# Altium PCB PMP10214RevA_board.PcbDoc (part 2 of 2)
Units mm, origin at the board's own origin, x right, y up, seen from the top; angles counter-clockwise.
Board outline 108.2 x 92.71 mm, 6 copper layers (Top Layer, MidLayer1, MidLayer2, MidLayer3, MidLayer4, Bottom Layer), stack 1.557 mm thick; 122 components, 44 nets, 289 pads, 1298 vias.
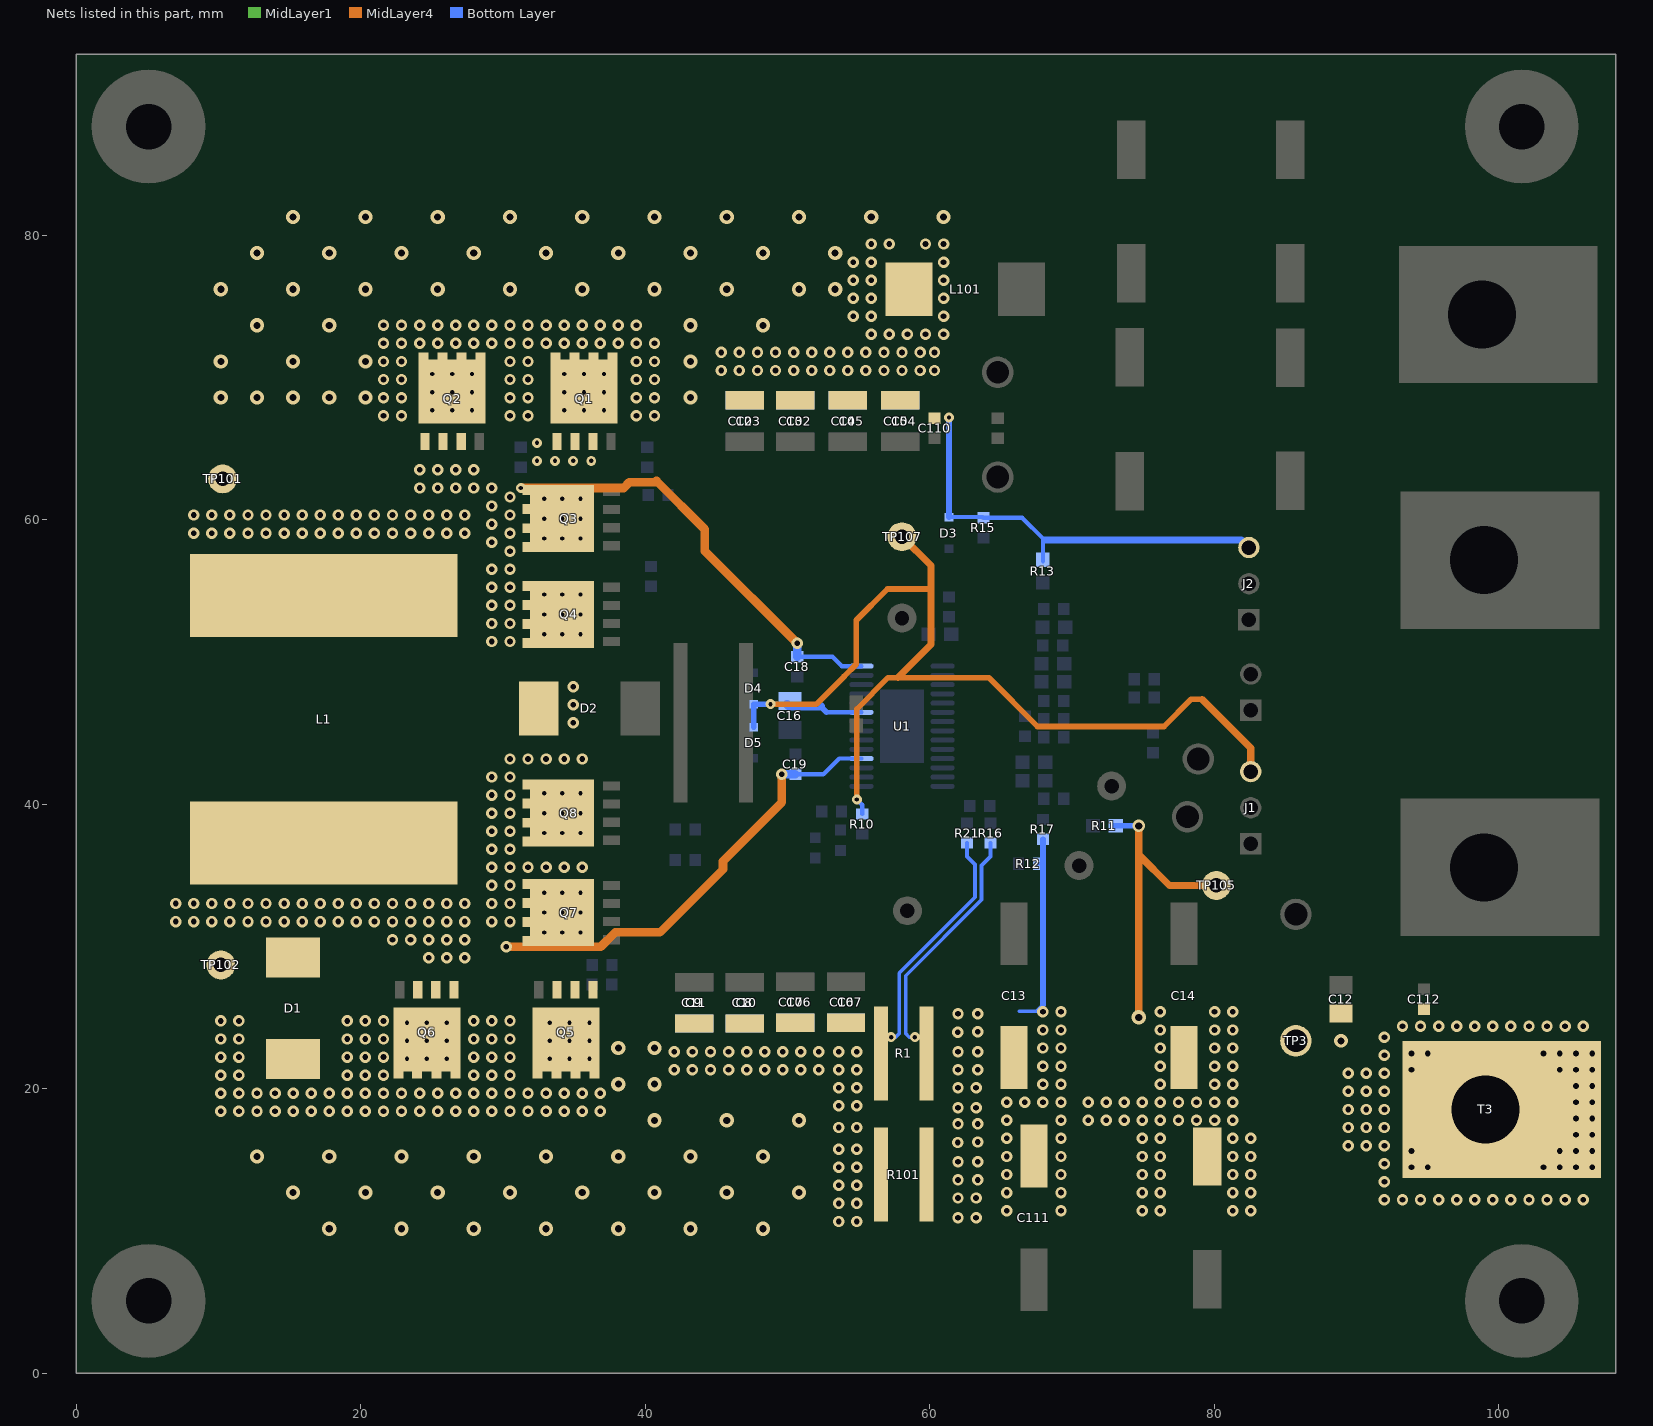
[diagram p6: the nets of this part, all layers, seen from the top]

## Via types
v1: diameter 0.8, hole 0.4, Top Layer to Bottom Layer, tented both sides, 696 vias
v2: diameter 0.8, hole 0.4, Top Layer to Bottom Layer, 220 vias
v3: diameter 0.7, hole 0.3, Top Layer to Bottom Layer, 142 vias
v4: diameter 0.813, hole 0.4, Top Layer to Bottom Layer, 112 vias
v5: diameter 1, hole 0.5, Top Layer to Bottom Layer, tented both sides, 74 vias
v6: diameter 0.7, hole 0.3, Top Layer to Bottom Layer, tented both sides, 25 vias
v7: diameter 0.6, hole 0.3, Top Layer to Bottom Layer, 15 vias
v8: diameter 0.7, hole 0.3, Top Layer to Bottom Layer, tented bottom, 5 vias
v9: diameter 0.6, hole 0.3, Top Layer to Bottom Layer, tented bottom, 3 vias
v10: diameter 0.965, hole 0.5, Top Layer to Bottom Layer, 2 vias
v11: diameter 0.65, hole 0.3, Top Layer to Bottom Layer, tented bottom, 2 vias
v12: diameter 0.67, hole 0.3, Top Layer to Bottom Layer, tented bottom, 1 vias
v13: diameter 0.9, hole 0.5, Top Layer to Bottom Layer, 1 vias

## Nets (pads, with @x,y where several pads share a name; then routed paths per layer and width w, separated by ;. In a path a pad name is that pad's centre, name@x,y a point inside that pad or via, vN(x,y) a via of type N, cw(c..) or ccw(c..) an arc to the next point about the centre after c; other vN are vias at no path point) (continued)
SW1: C18.1 D2.1 L1.1 Q1.1 Q1.2 Q1.3 Q2.1 Q2.2 Q2.3 Q3.5 Q3.6 Q3.7 Q3.8 Q3.9 Q4.5 Q4.6 Q4.7 Q4.8 Q4.9 TP101.1 U1.28 | length 31
  MidLayer4 w0.61: v3(31.242,62.23) 38.471,62.23 38.868,62.627 40.69,62.627 40.784,62.721 44.183,59.322 44.183,57.798 v2(50.673,51.308)
  Bottom Layer w0.305: C18.1@50.673,50.357 53.148,50.357 53.798,49.707 U1.28@55.189,49.707
  Bottom Layer w0.61: C18.1@50.673,50.357 v2(50.673,51.308)
  other v1: 34.925,45.72 34.925,46.99 34.925,48.26 29.21,51.435 30.48,51.435 29.21,52.705 30.48,52.705 29.21,53.975 30.48,53.975 29.21,55.245 30.48,55.245 29.21,56.515 30.48,56.515 30.48,57.785 29.21,58.42 8.255,59.055 9.525,59.055 12.065,59.055 14.605,59.055 17.145,59.055 19.685,59.055 22.225,59.055 24.765,59.055 26.035,59.055 27.305,59.055 30.48,59.055 29.21,59.69 8.255,60.325 9.525,60.325 12.065,60.325 14.605,60.325 17.145,60.325 19.685,60.325 22.225,60.325 24.765,60.325 26.035,60.325 27.305,60.325 30.48,60.325 29.21,60.96 30.48,61.595 24.13,62.23 25.4,62.23 26.67,62.23 27.94,62.23 29.21,62.23 24.13,63.5 25.4,63.5 26.67,63.5 27.94,63.5
  other v2: 10.795,59.055 13.335,59.055 15.875,59.055 18.415,59.055 20.955,59.055 23.495,59.055 10.795,60.325 13.335,60.325 15.875,60.325 18.415,60.325 20.955,60.325 23.495,60.325
  other v3: 32.893,51.943 34.163,51.943 35.433,51.943 32.893,53.34 34.163,53.34 35.433,53.34 32.893,54.737 34.163,54.737 35.433,54.737 32.893,58.674 34.163,58.674 35.433,58.674 32.893,60.071 34.163,60.071 35.433,60.071 32.893,61.468 34.163,61.468 35.433,61.468
  other v6: 32.385,64.135 33.655,64.135 34.925,64.135 36.195,64.135 32.385,65.405
SW2: C19.2 D1.2 L1.2 Q5.1 Q5.2 Q5.3 Q6.1 Q6.2 Q6.3 Q7.5 Q7.6 Q7.7 Q7.8 Q7.9 Q8.5 Q8.6 Q8.7 Q8.8 Q8.9 TP102.1 U1.18 | length 31.9
  MidLayer4 w0.61: v2(30.226,29.972) 36.857,29.972 37.873,30.988 41.021,30.988 45.45,35.417 45.45,35.984 49.592,40.126 v2(49.592,42.099)
  Bottom Layer w0.305: C19.2@50.546,42.099 52.513,42.099 53.621,43.207 U1.18@55.189,43.207
  Bottom Layer w0.61: v2(49.592,42.099) C19.2@50.546,42.099
  other v1: 24.765,29.21 26.035,29.21 27.305,29.21 22.225,30.48 23.495,30.48 24.765,30.48 26.035,30.48 27.305,30.48 6.985,31.75 8.255,31.75 9.525,31.75 12.065,31.75 14.605,31.75 17.145,31.75 19.685,31.75 22.225,31.75 24.765,31.75 26.035,31.75 27.305,31.75 29.21,31.75 30.48,31.75 6.985,33.02 8.255,33.02 9.525,33.02 12.065,33.02 14.605,33.02 17.145,33.02 19.685,33.02 22.225,33.02 24.765,33.02 26.035,33.02 27.305,33.02 29.21,33.02 30.48,33.02 29.21,34.29 30.48,34.29 29.21,35.56 30.48,35.56 31.75,35.56 33.02,35.56 34.29,35.56 35.56,35.56 29.21,36.83 30.48,36.83 29.21,38.1 30.48,38.1 29.21,39.37 30.48,39.37 29.21,40.64 30.48,40.64 29.21,41.91 30.48,41.91 30.48,43.18 31.75,43.18 33.02,43.18 34.29,43.18 35.56,43.18
  other v2: 10.795,31.75 13.335,31.75 15.875,31.75 18.415,31.75 20.955,31.75 23.495,31.75 10.795,33.02 13.335,33.02 15.875,33.02 18.415,33.02 20.955,33.02 23.495,33.02
  other v3: 32.893,30.988 34.163,30.988 35.433,30.988 32.893,32.385 34.163,32.385 35.433,32.385 32.893,33.782 34.163,33.782 35.433,33.782 32.893,37.973 34.163,37.973 35.433,37.973 32.893,39.37 34.163,39.37 35.433,39.37 32.893,40.767 34.163,40.767 35.433,40.767
VCC: C16.2 D4.2 D5.2 J1.3 R10.2 TP107.1 U1.23 | length 79.2
  MidLayer1 w0.254: v8@54.864,40.132 v8(54.864,40.332)
  MidLayer4 w0.4: v8(54.864,40.332) 54.864,46.702 57.057,48.895 57.748,48.895 64.135,48.895 67.564,45.466 76.454,45.466 78.359,47.371 79.121,47.371
  MidLayer4 w0.406: v6(48.789,47.033) 52.032,47.033 53.522,48.523 53.525,48.523 53.966,48.964 53.966,48.967 54.829,49.829 54.829,52.924 57.023,55.118 60.071,55.118
  MidLayer4 w0.5: 57.748,48.895 60.071,51.218 60.071,55.118 60.071,56.769 TP107.1@58.039,58.801 ; 79.121,47.371 82.55,43.942 J1.3@82.55,42.291
  Bottom Layer w0.305: 52.73,46.457 U1.23@55.189,46.457 ; v8(54.864,40.332) 55.245,39.951 R10.2@55.245,39.308
  Bottom Layer w0.406: D5.2@47.625,45.423 D4.2@47.625,47.033 v6(48.789,47.033) C16.2@49.954,47.033 ; 52.309,46.878 52.73,46.457
  Bottom Layer w0.61: C16.2@49.954,47.033 50.109,46.878 52.309,46.878
VIN: C2.1 C3.1 C4.1 C5.1 C102.1 C103.1 C104.1 C105.1 C110.1 D3.2 J2.3 L101.2 Q1.5 Q1.6 Q1.7 Q1.8 Q1.9 Q2.5 Q2.6 Q2.7 Q2.8 Q2.9 R13.2 R15.2 | length 30.5
  Bottom Layer w0.305: D3.2@61.341,60.184 R15.2@63.705,60.184 ; R15.2@63.754,60.136 66.483,60.136 67.945,58.674 ; R13.2@67.945,57.088 67.945,57.15 67.945,58.674 ; 68.056,58.563 67.945,58.674
  Bottom Layer w0.4: D3.2@61.341,60.184 v3(61.341,67.183)
  Bottom Layer w0.5: 68.056,58.563 81.899,58.563 J2.3@82.423,58.039
  other v1: 21.59,67.31 22.86,67.31 30.48,67.31 31.75,67.31 39.37,67.31 40.64,67.31 21.59,68.58 22.86,68.58 30.48,68.58 31.75,68.58 39.37,68.58 40.64,68.58 21.59,69.85 22.86,69.85 30.48,69.85 31.75,69.85 39.37,69.85 40.64,69.85 60.325,70.485 21.59,71.12 22.86,71.12 30.48,71.12 31.75,71.12 39.37,71.12 40.64,71.12 60.325,71.755 21.59,72.39 22.86,72.39 24.13,72.39 25.4,72.39 26.67,72.39 27.94,72.39 29.21,72.39 30.48,72.39 31.75,72.39 33.02,72.39 34.29,72.39 35.56,72.39 36.83,72.39 38.1,72.39 39.37,72.39 40.64,72.39 55.88,73.025 57.15,73.025 58.42,73.025 59.69,73.025 60.96,73.025 21.59,73.66 22.86,73.66 24.13,73.66 25.4,73.66 26.67,73.66 27.94,73.66 29.21,73.66 30.48,73.66 31.75,73.66 33.02,73.66 34.29,73.66 35.56,73.66 36.83,73.66 38.1,73.66 39.37,73.66 54.61,74.295 55.88,74.295 60.96,74.295 54.61,75.565 55.88,75.565 60.96,75.565 54.61,76.835 55.88,76.835 60.96,76.835 54.61,78.105 55.88,78.105 60.96,78.105 55.88,79.375 57.15,79.375 59.69,79.375 60.96,79.375
  other v2: 45.339,70.485 46.609,70.485 47.879,70.485 49.149,70.485 50.419,70.485 51.689,70.485 52.959,70.485 54.229,70.485 55.499,70.485 56.769,70.485 58.039,70.485 59.309,70.485 45.339,71.755 46.609,71.755 47.879,71.755 49.149,71.755 50.419,71.755 51.689,71.755 52.959,71.755 54.229,71.755 55.499,71.755 56.769,71.755 58.039,71.755 59.309,71.755
  other v3: 25.019,67.691 26.416,67.691 27.813,67.691 34.29,67.691 35.687,67.691 37.084,67.691 25.019,68.961 26.416,68.961 27.813,68.961 34.29,68.961 35.687,68.961 37.084,68.961 25.019,70.231 26.416,70.231 27.813,70.231 34.29,70.231 35.687,70.231 37.084,70.231
  other v5: 10.16,68.58 12.7,68.58 15.24,68.58 17.78,68.58 20.32,68.58 43.18,68.58 10.16,71.12 15.24,71.12 20.32,71.12 43.18,71.12 12.7,73.66 17.78,73.66 43.18,73.66 48.26,73.66 10.16,76.2 15.24,76.2 20.32,76.2 25.4,76.2 30.48,76.2 35.56,76.2 40.64,76.2 45.72,76.2 50.8,76.2 53.34,76.2 12.7,78.74 17.78,78.74 22.86,78.74 27.94,78.74 33.02,78.74 38.1,78.74 43.18,78.74 48.26,78.74 53.34,78.74 15.24,81.28 20.32,81.28 25.4,81.28 30.48,81.28 35.56,81.28 40.64,81.28 45.72,81.28 50.8,81.28 55.88,81.28 60.96,81.28
VOSNS+: C6.1 C7.1 C8.1 C9.1 C10.1 C11.1 C106.1 C107.1 D1.1 Q5.5 Q5.6 Q5.7 Q5.8 Q5.9 Q6.5 Q6.6 Q6.7 Q6.8 Q6.9 R1.1 R21.1 R101.1 | length 16.5
  Bottom Layer w0.254: v3(57.277,23.622) 57.585,23.622 57.839,23.876 57.839,28.128 63.173,33.462 63.173,35.76 62.611,36.322 R21.1@62.611,37.273
  other v1: 53.594,10.668 54.864,10.668 53.594,11.938 54.864,11.938 53.594,17.272 54.864,17.272 10.16,18.415 11.43,18.415 12.7,18.415 13.97,18.415 15.24,18.415 16.51,18.415 17.78,18.415 19.05,18.415 20.32,18.415 21.59,18.415 22.86,18.415 24.13,18.415 25.4,18.415 26.67,18.415 27.94,18.415 29.21,18.415 30.48,18.415 31.75,18.415 33.02,18.415 34.29,18.415 35.56,18.415 36.83,18.415 53.594,18.796 54.864,18.796 10.16,19.685 11.43,19.685 12.7,19.685 13.97,19.685 15.24,19.685 16.51,19.685 17.78,19.685 19.05,19.685 20.32,19.685 21.59,19.685 22.86,19.685 24.13,19.685 25.4,19.685 26.67,19.685 27.94,19.685 29.21,19.685 30.48,19.685 31.75,19.685 33.02,19.685 34.29,19.685 35.56,19.685 36.83,19.685 10.16,20.955 11.43,20.955 19.05,20.955 20.32,20.955 21.59,20.955 27.94,20.955 29.21,20.955 30.48,20.955 10.16,22.225 11.43,22.225 19.05,22.225 20.32,22.225 21.59,22.225 27.94,22.225 29.21,22.225 30.48,22.225 10.16,23.495 11.43,23.495 19.05,23.495 20.32,23.495 21.59,23.495 27.94,23.495 29.21,23.495 30.48,23.495 10.16,24.765 11.43,24.765 19.05,24.765 20.32,24.765 21.59,24.765 27.94,24.765 29.21,24.765 30.48,24.765
  other v2: 53.594,13.208 54.864,13.208 53.594,14.478 54.864,14.478 53.594,15.748 54.864,15.748 53.594,20.066 54.864,20.066 42.037,21.336 43.307,21.336 44.577,21.336 45.847,21.336 47.117,21.336 48.387,21.336 49.657,21.336 50.927,21.336 52.197,21.336 53.594,21.336 54.864,21.336 42.037,22.606 43.307,22.606 44.577,22.606 45.847,22.606 47.117,22.606 48.387,22.606 49.657,22.606 50.927,22.606 52.197,22.606 53.594,22.606 54.864,22.606
  other v3: 23.241,22.098 24.638,22.098 26.035,22.098 33.274,22.098 34.671,22.098 36.068,22.098 23.241,23.368 24.638,23.368 26.035,23.368 33.274,23.368 34.671,23.368 36.068,23.368 23.241,24.638 24.638,24.638 26.035,24.638 33.274,24.638 34.671,24.638 36.068,24.638
  other v5: 17.78,10.16 22.86,10.16 27.94,10.16 33.02,10.16 38.1,10.16 43.18,10.16 48.26,10.16 15.24,12.7 20.32,12.7 25.4,12.7 30.48,12.7 35.56,12.7 40.64,12.7 45.72,12.7 50.8,12.7 12.7,15.24 17.78,15.24 22.86,15.24 27.94,15.24 33.02,15.24 38.1,15.24 43.18,15.24 48.26,15.24 40.64,17.78 45.72,17.78 50.8,17.78 38.1,20.32 40.64,20.32 38.1,22.86 40.64,22.86
VOSNS-: C12.1 C13.1 C14.1 C111.1 C112.1 pad.0@79.502,15.24 R1.2 R11.2 R12.2 R16.1 R17.1 R101.2 T3.1 TP3.1 TP105.1 | length 52
  MidLayer4 w0.5: 74.676,36.449 v13(74.676,38.481)
  MidLayer4 w0.508: v5(74.676,25.019) 74.676,36.449 76.835,34.29 TP105.1@80.137,34.29
  Bottom Layer w0.254: v3(58.941,23.622) 58.547,23.622 58.293,23.876 58.293,27.94 63.627,33.274 63.627,35.687 64.262,36.322 R16.1@64.262,37.273 ; 66.294,25.44 67.477,25.44 67.945,25.908 ; R12.2@67.629,35.814 R12.2@67.945,35.814
  Bottom Layer w0.4: 67.945,25.908 67.945,35.814 R17.1@67.945,37.527 ; R11.2@72.848,38.481 v13(74.676,38.481)
  other v1: 65.405,11.43 69.215,11.43 74.93,11.43 76.2,11.43 81.28,11.43 82.55,11.43 91.948,12.192 93.218,12.192 94.488,12.192 95.758,12.192 97.028,12.192 98.298,12.192 99.568,12.192 100.838,12.192 102.108,12.192 103.378,12.192 104.648,12.192 105.918,12.192 65.405,12.7 69.215,12.7 74.93,12.7 76.2,12.7 81.28,12.7 82.55,12.7 91.948,13.462 65.405,13.97 69.215,13.97 74.93,13.97 76.2,13.97 81.28,13.97 82.55,13.97 91.948,14.732 65.405,15.24 69.215,15.24 74.93,15.24 76.2,15.24 81.28,15.24 82.55,15.24 65.405,16.51 69.215,16.51 74.93,16.51 76.2,16.51 81.28,16.51 82.55,16.51 65.405,17.78 69.215,17.78 71.12,17.78 72.39,17.78 73.66,17.78 74.93,17.78 76.2,17.78 77.47,17.78 78.74,17.78 80.01,17.78 81.28,17.78 65.405,19.05 66.675,19.05 67.945,19.05 69.215,19.05 71.12,19.05 72.39,19.05 73.66,19.05 74.93,19.05 76.2,19.05 77.47,19.05 78.74,19.05 80.01,19.05 81.28,19.05 67.945,20.32 69.215,20.32 76.2,20.32 80.01,20.32 81.28,20.32 67.945,21.59 69.215,21.59 76.2,21.59 80.01,21.59 81.28,21.59 91.948,22.352 67.945,22.86 69.215,22.86 76.2,22.86 80.01,22.86 81.28,22.86 91.948,23.622 67.945,24.13 69.215,24.13 76.2,24.13 80.01,24.13 81.28,24.13 93.218,24.384 94.488,24.384 95.758,24.384 97.028,24.384 98.298,24.384 99.568,24.384 100.838,24.384 102.108,24.384 103.378,24.384 104.648,24.384 105.918,24.384 67.945,25.4 69.215,25.4 76.2,25.4 80.01,25.4 81.28,25.4
  other v2: 61.976,10.922 63.246,10.922 61.976,12.319 63.246,12.319 61.976,13.589 63.373,13.589 61.976,14.859 63.373,14.859 89.408,16.002 90.678,16.002 91.948,16.002 61.967,16.22 63.373,16.256 89.408,17.272 90.678,17.272 91.948,17.272 61.976,17.526 63.373,17.526 89.408,18.542 90.678,18.542 91.948,18.542 61.976,18.669 63.246,18.669 89.408,19.812 90.678,19.812 91.948,19.812 61.976,20.066 63.246,20.066 89.408,21.082 90.678,21.082 91.948,21.082 61.976,21.336 63.373,21.336 61.976,22.606 63.373,22.606 61.967,23.967 63.373,24.003 61.976,25.273 63.373,25.273
  other v4: 93.853,14.478 94.996,14.478 103.124,14.478 104.267,14.478 105.41,14.478 106.553,14.478 93.853,15.621 104.267,15.621 105.41,15.621 106.553,15.621 105.41,16.764 106.553,16.764 105.41,17.907 106.553,17.907 105.41,19.05 106.553,19.05 105.41,20.193 106.553,20.193 93.853,21.336 104.267,21.336 105.41,21.336 106.553,21.336 93.853,22.479 94.996,22.479 103.124,22.479 104.267,22.479 105.41,22.479 106.553,22.479
  other v10: 88.9,23.368
pads on no net: H1.1 H2.1 H3.1 H4.1

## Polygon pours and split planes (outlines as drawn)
CSG on MidLayer4 "Top Layer-No Net 6" (solid, remove dead copper, pour order 70): 0.889,0.381 0.889,92.075 107.315,92.075 107.315,0.381
CSG on MidLayer3 "Top Layer-No Net 6" (solid, remove dead copper, pour order 55): 0.889,0.508 0.889,92.202 107.188,92.202 107.188,0.508
CSG on MidLayer1 "Top Layer-No Net" (solid, remove dead copper, pour order 86): 60.96,8.89 96.647,8.89 96.647,0.635 60.96,0.635
CSG on MidLayer1 "Top Layer-No Net" (solid, remove dead copper, pour order 82): 63.119,83.947 96.647,83.947 96.647,91.44 63.119,91.44
CSG on MidLayer1 "M4 3D STEP Bottom-No Net" (solid, remove dead copper, pour order 69): 45.101,66.167 107.188,66.167 107.188,47.625 90.187,47.625 90.187,45.085 107.188,45.085 107.188,26.67 41.783,26.67 41.783,31.606 45.101,34.924 45.101,38.72 45.142,45.72 45.103,52.466 45.102,57.023
SW2 on MidLayer1 "Top Layer-No Net 3" (solid, remove dead copper, pour order 59): 36.628,26.289 0.889,26.289 0.889,44.069 30.861,44.069 36.48,44.069
SW1 on MidLayer1 "Top Layer-No Net 4" (solid, remove dead copper, pour order 61): 37.592,44.831 37.592,66.04 0.889,66.04 0.889,45.974 30.099,45.974 31.242,44.831
CS on MidLayer1 "Top Overlay-No Net" (solid, remove dead copper, pour order 57): 36.957,26.289 41.402,26.289 41.402,31.877 44.831,35.306 44.831,45.085 43.173,45.085 43.173,46.355 44.831,46.355 44.831,66.04 36.957,66.04
VIN on MidLayer1 "Top Layer-No Net 2" (solid, remove dead copper, pour order 67): 61.595,66.675 0.889,66.675 0.889,75.946 17.145,92.202 61.595,92.202
VOSNS- on MidLayer1 "Top Layer-No Net 1" (solid, remove dead copper, pour order 65): 107.188,9.906 58.801,9.906 58.801,25.908 107.188,25.908
VOSNS+ on MidLayer1 "Top Layer-No Net" (solid, remove dead copper, pour order 63): 57.531,25.781 57.531,0.635 16.637,0.635 0.889,16.383 0.889,25.781
NetC1_1 on MidLayer1 "Top Layer-IN" (solid, remove dead copper, pour order 49): 62.992,66.675 62.992,83.185 107.188,83.185 107.188,66.675
CSG on Bottom Layer "Top Layer-No Net" (solid, remove dead copper, pour order 84): 60.96,8.89 96.647,8.89 96.647,0.635 60.96,0.635
CSG on Bottom Layer "Top Layer-No Net" (solid, remove dead copper, pour order 80): 63.119,83.947 96.647,83.947 96.647,91.44 63.119,91.44
CSG on Bottom Layer "Bottom Layer-No Net 1" (solid, remove dead copper, pour order 78): 107.188,66.167 107.188,47.752 90.17,47.752 90.17,45.323 103.997,45.323 107.188,48.514 107.188,26.67 41.866,26.67 41.866,31.833 45.084,35.051 45.142,35.109 45.142,44.847 45.142,44.888 45.339,45.085 46.373,45.085 46.373,46.33 45.265,46.33 45.175,46.42 45.142,46.453 45.142,56.896 45.142,57.337 45.084,57.395 45.084,66.167
CS on Bottom Layer "Top Overlay-No Net" (solid, remove dead copper, pour order 72): 36.957,26.469 37.137,26.289 41.402,26.289 41.402,31.819 44.889,35.306 44.889,66.04 36.957,66.04
CSG on Bottom Layer "Top Layer-No Net 5" (solid, remove dead copper, pour order 71): 74.803,55.626 74.803,39.64 67.42,39.427 67.507,44.195 68.961,44.195 68.961,55.626
VOSNS+ on Bottom Layer "Top Layer-No Net" (solid, remove dead copper, pour order 75): 57.531,25.781 57.531,0.635 16.637,0.635 0.889,16.383 0.889,25.781
VOSNS- on Bottom Layer "Top Layer-No Net 1" (solid, remove dead copper, pour order 76): 107.188,9.906 58.801,9.906 58.801,25.908 107.188,25.908
VIN on Bottom Layer "Top Layer-No Net 2" (solid, remove dead copper, pour order 77): 61.595,66.802 0.889,66.802 0.889,76.073 17.018,92.202 61.595,92.202
SW1 on Bottom Layer "Top Layer-No Net 4" (solid, remove dead copper, pour order 74): 36.576,44.831 36.576,66.04 0.889,66.04 0.889,45.974 30.099,45.974 31.242,44.831
SW2 on Bottom Layer "Top Layer-No Net 3" (solid, remove dead copper, pour order 73): 36.641,26.289 0.889,26.289 0.889,44.069 30.859,44.069 36.492,44.069
NetC1_1 on Bottom Layer "Top Layer-IN" (solid, remove dead copper, pour order 47): 62.992,66.675 62.992,83.185 107.188,83.185 107.188,66.675
CSG on Top Layer "Top Layer-No Net" (solid, remove dead copper, pour order 83): 60.96,8.89 96.647,8.89 96.647,0.635 60.96,0.635
CSG on Top Layer "Top Layer-No Net" (solid, remove dead copper, pour order 79): 63.119,83.947 96.647,83.947 96.647,91.44 63.119,91.44
CS on Top Layer "Top Overlay-No Net" (solid, remove dead copper, pour order 44): 36.957,26.289 41.402,26.289 41.402,31.877 44.831,35.306 44.831,66.04 36.957,66.04
SW2 on Top Layer "Top Layer-No Net 3" (solid, remove dead copper, pour order 46): 36.604,26.289 0.889,26.289 0.889,44.069 30.861,44.069 36.455,44.069
SW1 on Top Layer "Top Layer-No Net 4" (solid, remove dead copper, pour order 50): 36.576,44.831 36.576,66.167 0.889,66.167 0.889,45.974 30.099,45.974 31.242,44.831
VOSNS+ on Top Layer "Top Layer-No Net" (solid, remove dead copper, pour order 51): 57.531,25.781 57.531,0.635 16.637,0.635 0.889,16.383 0.889,25.781
CSG on Top Layer "M4 3D STEP Bottom-No Net" (solid, remove dead copper, pour order 54): 45.085,66.167 107.188,66.167 107.188,47.752 90.17,47.752 90.17,45.212 107.188,45.212 107.188,26.67 41.834,26.67 41.834,31.801 45.084,35.051 45.084,38.847 45.086,52.593 45.085,57.15
VOSNS- on Top Layer "Top Layer-No Net 1" (solid, remove dead copper, pour order 52): 107.188,9.906 58.801,9.906 58.801,25.908 107.188,25.908
VIN on Top Layer "Top Layer-No Net 2" (solid, remove dead copper, pour order 53): 61.595,66.675 0.889,66.675 0.889,76.073 17.018,92.202 61.595,92.202
NetC1_1 on Top Layer "Top Layer-IN" (solid, remove dead copper, pour order 45): 62.992,66.675 62.992,83.185 107.188,83.185 107.188,66.675
NetC1_1 on MidLayer2 "Top Layer-IN" (solid, remove dead copper, pour order 48): 62.992,66.675 62.992,83.185 107.188,83.185 107.188,66.675
VOSNS+ on MidLayer2 "Top Layer-No Net" (solid, remove dead copper, pour order 62): 57.531,25.781 57.531,0.635 16.637,0.635 0.889,16.383 0.889,25.781
VOSNS- on MidLayer2 "Top Layer-No Net 1" (solid, remove dead copper, pour order 64): 107.188,9.906 58.801,9.906 58.801,25.908 107.188,25.908
VIN on MidLayer2 "Top Layer-No Net 2" (solid, remove dead copper, pour order 66): 61.595,66.675 0.889,66.675 0.889,75.946 17.145,92.202 61.595,92.202
CS on MidLayer2 "Top Overlay-No Net" (solid, remove dead copper, pour order 56): 36.957,26.289 41.402,26.289 41.402,31.877 44.831,35.306 44.831,45.085 43.173,45.085 43.173,46.355 44.831,46.355 44.831,66.04 36.957,66.04
SW1 on MidLayer2 "Top Layer-No Net 4" (solid, remove dead copper, pour order 60): 37.592,44.831 37.592,66.04 0.889,66.04 0.889,45.974 30.099,45.974 31.242,44.831
SW2 on MidLayer2 "Top Layer-No Net 3" (solid, remove dead copper, pour order 58): 36.628,26.289 0.889,26.289 0.889,44.069 30.861,44.069 36.48,44.069
CSG on MidLayer2 "M4 3D STEP Bottom-No Net" (solid, remove dead copper, pour order 68): 45.101,66.167 107.188,66.167 107.188,47.625 90.187,47.625 90.187,45.085 107.188,45.085 107.188,26.67 41.783,26.67 41.783,31.606 45.101,34.924 45.101,38.72 45.142,45.72 45.103,52.466 45.102,57.023
CSG on MidLayer2 "Top Layer-No Net" (solid, remove dead copper, pour order 81): 63.119,83.947 96.647,83.947 96.647,91.44 63.119,91.44
CSG on MidLayer2 "Top Layer-No Net" (solid, remove dead copper, pour order 85): 60.96,8.89 96.647,8.89 96.647,0.635 60.96,0.635

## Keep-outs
Keep-Out Layer:
  text ".Layer_Name" at 14.656,-21.806 h1.52

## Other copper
Top Layer:
  pour cut-out: 58.512,19.649 57.912,19.649 57.912,26.324 58.512,26.324
  pour cut-out: 107.442,45.323 90.17,45.323 90.17,47.752 90.186,47.768 107.442,47.768
  pour cut-out: 46.609,45.085 45.339,45.085 45.212,44.958 45.085,44.847 44.774,44.847 44.577,45.085 43.053,45.085 43.053,46.355 43.078,46.33 44.577,46.355 44.774,46.509 45.085,46.509 45.265,46.33 46.609,46.33
  text ".Layer_Name" at 14.656,-21.806 h1.52
MidLayer3:
  pour cut-out: 45.069,46.368 45.774,46.368 45.974,46.169 45.974,45.296 45.779,45.098 45.069,45.098
  pour cut-out: 107.442,45.323 90.17,45.323 90.17,47.752 90.186,47.768 107.442,47.768
  text ".layer_Name" at 14.605,-21.844 h1.52
MidLayer1:
  pour cut-out: 107.442,45.323 90.17,45.323 90.17,47.752 90.186,47.768 107.442,47.768
  pour cut-out: 57.785,23.114 57.023,23.114 56.769,23.368 56.769,23.876 57.023,24.13 57.785,24.13
  pour cut-out: 58.547,24.13 59.309,24.13 59.563,23.876 59.563,23.368 59.309,23.114 58.547,23.114
  pour cut-out: 45.069,46.368 45.774,46.368 45.974,46.169 45.974,45.296 45.779,45.098 45.069,45.098
  text ".layer_Name" at 14.605,-21.844 h1.52
MidLayer4:
  pour cut-out: 107.442,45.323 90.17,45.323 90.17,47.752 90.186,47.768 107.442,47.768
  pour cut-out: 45.069,46.342 45.774,46.342 45.974,46.142 45.974,45.269 45.779,45.072 45.069,45.072
  text ".layer_Name" at 14.605,-21.844 h1.52
MidLayer2:
  pour cut-out: 45.069,46.342 45.774,46.342 45.974,46.142 45.974,45.269 45.779,45.072 45.069,45.072
  pour cut-out: 107.442,45.404 90.229,45.45 90.229,47.736 90.245,47.752 107.442,47.752
  pour cut-out: 44.831,45.212 44.069,45.212 43.815,45.466 43.815,45.974 44.069,46.228 44.831,46.228
  text ".layer_Name" at 14.605,-21.844 h1.52
Bottom Layer:
  pour cut-out: 44.831,45.212 44.069,45.212 43.815,45.466 43.815,45.974 44.069,46.228 44.831,46.228
  pour cut-out: 57.785,23.114 57.023,23.114 56.769,23.368 56.769,23.876 57.023,24.13 57.785,24.13
  pour cut-out: 58.42,24.13 59.182,24.13 59.436,23.876 59.436,23.368 59.182,23.114 58.42,23.114
  pour cut-out: 45.069,46.343 45.774,46.343 45.974,46.143 45.974,45.27 45.779,45.073 45.069,45.073
  pour cut-out: 107.442,45.307 90.229,45.307 90.229,47.736 90.245,47.752 107.442,47.752
  pour cut-out: 53.045,37.486 54.245,37.486 54.245,36.147 54.127,36.135 54.076,36.14 53.086,36.14
  pour cut-out: 44.45,45.72 44.45,41.148 44.831,40.767 44.831,45.72
  text ".Layer_Name" at 14.656,-21.806 h1.52

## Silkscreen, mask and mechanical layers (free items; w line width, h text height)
Top Overlay:
  text "VIN" at 96.266,80.518 h1.78
  text "+" at 102.997,80.137 h2.54
  text "-" at 103.124,62.611 h2.54
  text "EN" at 81.407,60.325 h1.02
  text "ON" at 78.232,57.785 h1.02
  text "VCC" at 61.066,57.655 h0.9 r90
  text "BIAS" at 61.087,52.668 h0.9 r90
  text "OFF" at 77.851,52.451 h1.02
  text "DITH" at 85.725,46.99 h1.02
  text "OFF" at 90.678,46.99 h1.02
  text "PG" at 76.835,42.672 h0.8 r90
  text "CCM hickup disabled" at 85.09,42.418 h1.02
  text "AGND" at 70.866,39.497 h0.9 r90
  text "MODE" at 86.106,38.1 h1.02 r90
  text "sync" at 80.645,37.211 h0.8 r90
  text "DCM" at 85.217,36.449 h1.02
  text "NWA" at 68.385,34.745 h0.9 r90
  text "VOUT" at 83.058,32.258 h0.9 r90
  text "PGND" at 56.896,29.845 h0.8
  text "-" at 103.886,27.305 h2.54
  text "VOUT" at 93.98,9.652 h1.78
  text "+" at 104.902,9.398 h2.54
  text "'.PCB_Layout''.PCB_Rev'" at 23.749,1.778 h1.52
  text ".Layer_Name" at 14.656,-21.806 h1.52
Bottom Overlay:
  lines w0.178: 50.546,38.227 50.546,38.608 51.181,39.243 ; 51.181,39.243 51.181,38.862 50.8,39.243 51.181,39.243
  text ".Layer_Name" at 14.656,-21.806 h1.52
Top Paste:
  text ".Layer_Name" at 14.656,-21.806 h1.52
Bottom Paste:
  text ".Layer_Name" at 14.656,-21.806 h1.52
Top Solder:
  text ".Layer_Name" at 14.656,-21.806 h1.52
  text ".Layer_Name" at 14.656,-21.806 h1.52
Bottom Solder:
  text ".Layer_Name" at 14.656,-21.806 h1.52
Drill Guide:
  text ".Layer_Name" at 14.656,-21.806 h1.52
M1 Board Outline:
  the board outline again, w0.203
  text ".Layer_Name" at 14.656,-21.806 h1.52
M2 Board Dimensions:
  rectangle: 0,-7.252 3.175,-4.077
  rectangle: 3.175,-10.427 12.7,-7.252
  lines w0.178: 0,-7.252 25.4,-7.252 ; 3.175,-10.427 3.175,-4.077 ; 6.35,-10.427 6.35,-4.077 ; 12.7,-10.427 12.7,-4.077 ; 19.05,-10.427 19.05,-4.077 ; 0,-10.427 25.4,-10.427 25.4,-4.077 0,-4.077 0,-10.427
  text ".Layer_Name" at 14.656,-21.806 h1.52
M3 3D STEP Top:
  text ".Layer_Name" at 14.656,-21.806 h1.52
M4 3D STEP Bottom:
  text ".Layer_Name" at 14.656,-21.806 h1.52
M5 Assembly Top:
  lines w0.254: -7.417,-23.626 160.223,-23.626 ; -7.417,-18.462 160.274,-18.462 ; -7.417,-13.297 -7.417,-28.791 94.31,-28.791 160.274,-28.791 160.274,-13.297 -7.404,-13.297 -7.404,-28.791 32.614,-28.791 ; 55.194,-28.791 55.194,-13.297 ; 87.376,-18.462 87.376,-13.297 ; 108.712,-18.462 108.712,-13.297 ; 124.511,-28.956 124.511,-23.804
  text "COMPONENTS MARKED 'DNP' SHOULD NOT BE POPULATED." at 29.299,-8.09 h1.52
  text "ASSEMBLY VARIANT:" at 29.286,-11.024 h1.52
  text ".VariantName" at 55.601,-11.024 h1.52
  text "PCB VIEWED FROM TOP SIDE" at -5.804,-16.654 h1.52
  text "BOARD #:" at 57.099,-16.654 h1.52
  text ".PRJ_Number" at 70.955,-16.654 h1.52
  text "REV:" at 92.405,-16.654 h1.52
  text ".PCB_Rev" at 99.809,-16.654 h1.52
  text "SVN REV:" at 113.69,-16.654 h1.52
  text ".VersionControl_RevNumber" at 126.543,-16.654 h1.52
  text "IGNORE ->" at -5.804,-21.806 h1.52
  text "PLOT NAME =" at -5.804,-27.034 h1.52
  text ".plot_File_Name" at 14.656,-27.034 h1.52
  text "GENERATED    :" at 57.15,-27.034 h1.52
  text ".Print_Date" at 79.235,-27.034 h1.52
  text ".Print_Time" at 97.752,-27.034 h1.52
  text "TEXAS INSTRUMENTS" at 129.87,-27.034 h1.52
M6 Assembly Bottom:
  lines w0.254: -7.429,-18.474 160.261,-18.474 ; -7.379,-23.639 160.261,-23.639 ; 28.334,-28.969 28.334,-23.817 ; 44.133,-18.474 44.133,-13.31 ; 65.468,-18.474 65.468,-13.31 ; 97.65,-28.804 97.65,-13.31 ; 120.231,-28.804 160.249,-28.804 160.249,-13.31 -7.429,-13.31 -7.429,-28.804 58.534,-28.804 160.261,-28.804 160.261,-13.31
  text "COMPONENTS MARKED 'DNP' SHOULD NOT BE POPULATED." at 154.991,-8.077 h1.52
  text ".VariantName" at 128.473,-11.024 h1.52
  text "ASSEMBLY VARIANT:" at 154.864,-11.024 h1.52
  text ".VersionControl_RevNumber" at 26.302,-16.667 h1.52
  text "SVN REV:" at 39.154,-16.667 h1.52
  text ".PCB_Rev" at 53.035,-16.667 h1.52
  text "REV:" at 60.439,-16.667 h1.52
  text ".PRJ_Number" at 81.89,-16.667 h1.52
  text "BOARD #:" at 95.745,-16.667 h1.52
  text "PCB VIEWED FROM BOTTOM SIDE" at 158.648,-16.667 h1.52
  text "IGNORE ->" at 64.715,-21.806 h1.52
  text "TEXAS INSTRUMENTS" at 22.974,-27.047 h1.52
  text ".Print_Time" at 55.093,-27.047 h1.52
  text ".Print_Date" at 73.609,-27.047 h1.52
  text "GENERATED    :" at 95.694,-27.047 h1.52
  text ".plot_File_Name" at 138.189,-27.047 h1.52
  text "PLOT NAME =" at 158.648,-27.047 h1.52
M9 Title Sheet:
  drawing of 57 lines, arcs and shapes, not listed
  text "1" at 18.792,204.127 h1.78
  text "2" at 82.182,204.127 h1.78
  text "3" at 145.411,204.127 h1.78
  text "4" at 209.08,204.127 h1.78
  text "5" at 272.555,204.127 h1.78
  text "6" at 336.182,204.127 h1.78
  text "A" at -10.579,175.095 h1.78
  text "A" at 365.341,175.095 h1.78
  text "B" at -10.579,114.643 h1.78
  text "B" at 365.341,114.643 h1.78
  text "C" at -10.579,54.318 h1.78
  text "C" at 365.341,54.318 h1.78
  text "PROJECT TITLE:" at 288.125,7.048 h1.14
  text ".PRJ_Title" at 289.395,3.662 h1.78
  text "DESIGNED FOR:" at 288.125,-0.597 h1.14
  text ".PRJ_Customer" at 289.395,-4.153 h1.78
  text "D" at -10.579,-5.88 h1.78
  text "D" at 365.341,-5.88 h1.78
  text "FILE NAME:" at 288.125,-8.217 h1.14
  text ".PCB_File_Name_No_Path" at 289.395,-11.265 h1.78
  text "Texas Instruments (TI) and/or its licensors do not warrant the accuracy or completeness of this specification" at 161.9,-15.376 h1.14
  text "ENGINEER:" at 288.125,-15.583 h1.14
  text "LAYOUT BY:" at 326.352,-15.583 h1.14
  text "or any information contained therein. TI and/or its licensors do not warrant that this design will meet" at 160.757,-18.237 h1.14
  text ".PRJ_Engineer" at 289.395,-19.52 h1.78
  text ".PCB_Layout" at 327.635,-19.52 h1.78
  text "the specifications, will be suitable for your application or fit for any particular purpose, or will operate in" at 160.757,-21.099 h1.14
  text ".Layer_Name" at 14.656,-21.806 h1.52
  text "ALTIUM DESIGNER VERSION:" at 326.352,-23.457 h1.14
  text "an implementation. TI and/or its licensors do not warrant that the design is production worthy. You should" at 160.757,-23.961 h1.14
  text "completely validate and test your design implementation to confirm the system functionality for your application." at 161.9,-26.822 h1.14
  text ".print_Scale" at 289.395,-26.843 h1.78
  text ".Application_BuildNumber" at 327.635,-26.843 h1.78
  text "1" at 18.792,-32.093 h1.78
  text "2" at 82.182,-32.093 h1.78
  text "3" at 145.411,-32.093 h1.78
  text "4" at 209.08,-32.093 h1.78
  text "5" at 272.555,-32.093 h1.78
  text "6" at 336.182,-32.093 h1.78
M10 Fab Notes:
  drawing of 185 lines, arcs and shapes, not listed
  text "DESIGN INFORMATION" at 314.478,150.114 h1.52
  text "MIN. TRACK WIDTH:" at 298.106,145.542 h1.52
  text "8" at 325.951,145.542 h1.52
  text "MIL" at 329.881,145.542 h1.52
  text "MIN. CLEARANCE:" at 298.106,142.189 h1.52
  text "0.2" at 324.427,142.189 h1.52
  text "mm" at 329.881,142.189 h1.52
  text "MIN. VIA PAD SIZE:" at 298.106,138.836 h1.52
  text "24" at 325.189,138.836 h1.52
  text "MIL" at 329.881,138.836 h1.52
  text "0.05mm (2MIL)" at 315.759,135.237 h1.52
  text "MINIMUM ANNULAR RING" at 289.744,135.128 h1.52
  text "EXTERNAL" at 333.742,135.128 h1.52
  text "PER" at 294.824,132.131 h1.52
  text "IPC-D-275 CLASS 2 LEVEL C" at 300.412,132.131 h1.52
  text "MIL, HOLES" at 338.213,129.279 h1.52
  text "+/-" at 328.244,129.261 h1.52
  text "+/-" at 349.936,129.261 h1.52
  text "REGISTRATION TOLERANCES:" at 289.744,129.134 h1.52
  text "METAL" at 320.218,129.134 h1.52
  text "5" at 334.853,129.134 h1.52
  text "3" at 356.012,129.134 h1.52
  text "MIL" at 358.964,129.134 h1.52
  text "MATERIAL:" at 287.844,123.813 h1.52
  text "FR-4 High Tg" at 312.9,120.249 h1.52
  text "FR-408" at 298.538,120.031 h1.52
  text "X" at 309.003,120.031 h1.52
  text "OTHER" at 336.333,120.031 h1.52
  text "62 MIL (1.6mm) +/-10%" at 306.668,115.898 h1.52
  text "THICKNESS:" at 289.744,115.789 h1.52
  text "X" at 303.413,115.789 h1.52
  text "OTHER" at 339.305,115.789 h1.52
  text "TOLERANCE:" at 289.744,111.776 h1.52
  text "X" at 311.062,111.776 h1.52
  text "ANSI IPC-6012 TYPE 3 CLASS 2" at 315.81,111.776 h1.52
  text "OTHER +/-" at 315.81,107.814 h1.52
  text "BOW & TWIST:" at 289.744,103.826 h1.52
  text "X" at 311.062,103.826 h1.52
  text "ANSI IPC-6012 TYPE 3 CLASS 2" at 315.81,103.826 h1.52
  text "OTHER +/-" at 315.81,99.8 h1.52
  text "DRILLING:" at 287.844,96.282 h1.52
  text "REFERENCE:" at 289.744,93.31 h1.52
  text "X" at 306.209,93.31 h1.52
  text "AS SHOWN" at 310.958,93.31 h1.52
  text "X" at 329.094,93.31 h1.52
  text "NC_DRILL FILES" at 332.574,93.31 h1.52
  text "PTH MIN COPPER THICKNESS:" at 289.744,89.297 h1.52
  text "X" at 324.039,89.297 h1.52
  text "1MIL" at 327.519,89.297 h1.52
  text "OTHER" at 340.143,89.297 h1.52
  text "BOARD FINISH:" at 287.844,85.259 h1.52
  text "SILKSCREEN:" at 291.787,82.261 h1.52
  text "X" at 315.886,82.261 h1.52
  text "TOP" at 319.086,82.261 h1.52
  text "X" at 328.84,82.261 h1.52
  text "BOTTOM" at 332.066,82.261 h1.52
  text "SILKSCREEN COLOR:" at 291.787,78.02 h1.52
  text "X" at 315.86,78.02 h1.52
  text "WHITE" at 319.086,78.02 h1.52
  text "OTHER" at 332.066,78.02 h1.52
  text "SOLDER RESIST COLOR:" at 291.787,73.702 h1.52
  text "X" at 306.208,69.658 h1.52
  text "GREEN" at 309.434,69.658 h1.52
  text "BLUE" at 324.446,69.658 h1.52
  text "OTHER" at 338.111,69.658 h1.52
  text "IMMERSION GOLD (ENIG)" at 314.794,64.87 h1.52
  text "ENEPIG" at 348.767,64.786 h1.52
  text "SURFACE FINISH:" at 287.844,64.761 h1.52
  text "X" at 310.045,64.761 h1.52
  text "IMM. TIN/SILVER OR EQUIV" at 296.215,60.773 h1.52
  text "OTHER" at 332.574,60.773 h1.52
  text "ARRAY/PANEL:" at 287.844,56.226 h1.52
  text "CUT AND TRIM PER MECH LAYER 1" at 314.794,56.118 h1.52
  text "X" at 331.978,52.324 h1.52
  text "N.C. ROUTE" at 314.794,52.264 h1.52
  text "V. SCORE" at 336.79,52.264 h1.52
  text "CERTIFICATION:" at 287.844,48.784 h1.52
  text "MATERIALS AND WORKMANSHIP FOR ALL PCBS" at 306.259,48.784 h1.52
  text "TO MEET OR EXCEED THE REQUIREMENTS OF:" at 306.259,46.295 h1.52
  text "X" at 296.773,42.828 h1.52
  text "ANSI IPC-A-600F CLASS ->" at 300.303,42.828 h1.52
  text "X" at 341.935,42.828 h1.52
  text "2" at 344.956,42.828 h1.52
  text "1" at 336.955,42.79 h1.52
  text "3" at 353.948,42.79 h1.52
  text "X" at 296.825,38.777 h1.52
  text "UL 94V-0" at 300.303,38.777 h1.52
  text "X" at 317.45,38.777 h1.52
  text "RoHS" at 320.928,38.777 h1.52
  text "OTHER" at 337.296,38.777 h1.52
  text "PER ORDER" at 347.381,38.777 h1.52
  text "ADDITIONAL REQUIREMENTS:" at 287.844,35.195 h1.52
  text "MICROSECTION:" at 289.744,32.274 h1.52
  text "YES" at 312.749,32.274 h1.52
  text "REQUIRED" at 334.631,28.308 h1.52
  text "BARE BOARD ELEC. TEST:" at 289.744,28.236 h1.52
  text "NONE" at 322.909,28.236 h1.52
  text "X" at 331.405,28.236 h1.52
  text "PER ORDER" at 349.668,28.236 h1.52
  text "MANUFACTURER'S UL:" at 289.744,24.248 h1.52
  text "RAIL" at 319.353,24.139 h1.52
  text "METAL" at 331.845,24.139 h1.52
  text "X" at 341.376,24.13 h1.52
  text "SILK" at 344.842,24.139 h1.52
  text ".Layer_Name" at 14.656,-21.806 h1.52
M11 Gerber Information:
  lines w0.254: -7.417,-23.626 160.223,-23.626 ; -7.417,-18.462 160.274,-18.462 ; -7.417,-13.297 -7.417,-28.791 94.31,-28.791 160.274,-28.791 160.274,-13.297 -7.404,-13.297 -7.404,-28.791 32.614,-28.791 ; 55.194,-28.791 55.194,-13.297 ; 87.376,-18.462 87.376,-13.297 ; 108.712,-18.462 108.712,-13.297 ; 124.511,-28.956 124.511,-23.804
  text "ALL ARTWORK VIEWED FROM TOP SIDE" at -5.804,-16.654 h1.52
  text "BOARD #:" at 57.099,-16.654 h1.52
  text ".PRJ_Number" at 70.955,-16.654 h1.52
  text "REV:" at 92.405,-16.654 h1.52
  text ".PCB_Rev" at 99.809,-16.654 h1.52
  text "SVN REV:" at 113.69,-16.654 h1.52
  text ".VersionControl_RevNumber" at 126.543,-16.654 h1.52
  text "LAYER NAME =" at -5.804,-21.806 h1.52
  text "PLOT NAME =" at -5.804,-27.034 h1.52
  text ".plot_File_Name" at 14.656,-27.034 h1.52
  text "GENERATED    :" at 57.15,-27.034 h1.52
  text ".Print_Date" at 79.235,-27.034 h1.52
  text ".Print_Time" at 97.752,-27.034 h1.52
  text "TEXAS INSTRUMENTS" at 129.87,-27.034 h1.52
M12 Stackup:
  drawing of 399 lines, arcs and shapes, not listed
  text "Layer" at 249.458,199.898 h1.52
  text "Name" at 259.87,199.898 h1.52
  text "Material" at 283.486,199.898 h1.52
  text "Thickness" at 305.324,199.898 h1.52
  text "Constant" at 321.83,199.898 h1.52
  text "Board Layer Stack" at 336.304,199.898 h1.52
  text "1" at 249.458,196.85 h1.52
  text "Top Overlay" at 259.87,196.85 h1.52
  text "2" at 249.458,193.802 h1.52
  text "Top Solder" at 259.87,193.802 h1.52
  text "Solder Resist" at 283.486,193.802 h1.52
  text "0.40mil" at 305.324,193.802 h1.52
  text "3.5" at 321.83,193.802 h1.52
  text "3" at 249.458,190.754 h1.52
  text "Top Layer" at 259.87,190.754 h1.52
  text "Copper" at 283.486,190.754 h1.52
  text "2.80mil" at 305.324,190.754 h1.52
  text "4" at 249.458,187.706 h1.52
  text "Dielectric1" at 259.87,187.706 h1.52
  text "FR-4" at 283.486,187.706 h1.52
  text "8.90mil" at 305.324,187.706 h1.52
  text "4.2" at 321.83,187.706 h1.52
  text "5" at 249.458,184.658 h1.52
  text "MidLayer1" at 259.87,184.658 h1.52
  text "Copper" at 283.486,184.658 h1.52
  text "2.80mil" at 305.324,184.658 h1.52
  text "6" at 249.458,181.61 h1.52
  text "Dielectric2" at 259.87,181.61 h1.52
  text "FR-4" at 283.486,181.61 h1.52
  text "8.90mil" at 305.324,181.61 h1.52
  text "4.8" at 321.83,181.61 h1.52
  text "7" at 249.458,178.562 h1.52
  text "MidLayer2" at 259.87,178.562 h1.52
  text "Copper" at 283.486,178.562 h1.52
  text "2.80mil" at 305.324,178.562 h1.52
  text "8" at 249.458,175.514 h1.52
  text "Dielectric3" at 259.87,175.514 h1.52
  text "FR-4" at 283.486,175.514 h1.52
  text "8.90mil" at 305.324,175.514 h1.52
  text "4.2" at 321.83,175.514 h1.52
  text "9" at 249.458,172.466 h1.52
  text "MidLayer3" at 259.87,172.466 h1.52
  text "Copper" at 283.486,172.466 h1.52
  text "2.80mil" at 305.324,172.466 h1.52
  text "10" at 249.458,169.418 h1.52
  text "Dielectric4" at 259.87,169.418 h1.52
  text "FR-4" at 283.486,169.418 h1.52
  text "8.90mil" at 305.324,169.418 h1.52
  text "4.8" at 321.83,169.418 h1.52
  text "11" at 249.458,166.37 h1.52
  text "MidLayer4" at 259.87,166.37 h1.52
  text "Copper" at 283.486,166.37 h1.52
  text "2.80mil" at 305.324,166.37 h1.52
  text "12" at 249.458,163.322 h1.52
  text "Dielectric5" at 259.87,163.322 h1.52
  text "FR-4" at 283.486,163.322 h1.52
  text "8.90mil" at 305.324,163.322 h1.52
  text "4.8" at 321.83,163.322 h1.52
  text "13" at 249.458,160.274 h1.52
  text "Bottom Layer" at 259.87,160.274 h1.52
  text "Copper" at 283.486,160.274 h1.52
  text "2.80mil" at 305.324,160.274 h1.52
  text "14" at 249.458,157.226 h1.52
  text "Bottom Solder" at 259.87,157.226 h1.52
  text "Solder Resist" at 283.486,157.226 h1.52
  text "0.40mil" at 305.324,157.226 h1.52
  text "3.5" at 321.83,157.226 h1.52
  text "15" at 249.458,154.178 h1.52
  text "Bottom Overlay" at 259.87,154.178 h1.52
  text ".Layer_Name" at 14.656,-21.806 h1.52
M13 Component Bodies Top:
  text ".Layer_Name" at 14.656,-21.806 h1.52
M14 Component Bodies Bottom:
  text ".Layer_Name" at 14.656,-21.806 h1.52
M15 Courtyards Top:
  text ".Layer_Name" at 14.656,-21.806 h1.52
M16 Courtyards Bottom:
  text ".Layer_Name" at 14.656,-21.806 h1.52
Drill Drawing:
  lines w0.254: 194.085,32.872 194.437,32.872 194.788,32.521 195.14,32.872 195.491,32.872 195.14,33.224 195.491,33.575 195.14,33.575 194.788,33.926 194.437,33.575 194.085,33.575 194.437,33.224 194.085,32.872 ; 194.085,36.035 194.437,36.035 194.437,35.683 195.14,35.683 195.14,36.035 195.491,36.035 195.491,36.737 195.14,36.737 195.14,37.089 194.437,37.089 194.437,36.737 194.085,36.737 194.085,36.035 ; 194.085,38.845 194.788,39.197 195.491,38.845 195.14,39.548 195.491,40.251 194.788,39.9 194.085,40.251 194.437,39.548 194.085,38.845 ; 194.085,42.008 195.491,42.008 195.491,43.413 194.085,43.413 194.085,42.008 ; 194.085,48.332 194.085,48.684 194.437,49.035 194.085,49.386 194.085,49.738 194.437,49.738 194.788,49.386 195.14,49.738 195.491,49.738 195.491,49.386 195.14,49.035 195.491,48.684 195.491,48.332 195.14,48.332 194.788,48.684 194.437,48.332 194.085,48.332 ; 194.367,33.013 194.577,33.013 194.788,32.802 194.999,33.013 195.21,33.013 194.999,33.224 195.21,33.434 194.999,33.434 194.788,33.645 194.577,33.434 194.367,33.434 194.577,33.224 194.367,33.013 ; 194.367,36.175 194.577,36.175 194.577,35.964 194.999,35.964 194.999,36.175 195.21,36.175 195.21,36.597 194.999,36.597 194.999,36.808 194.577,36.808 194.577,36.597 194.367,36.597 194.367,36.175 ; 194.367,39.127 194.788,39.337 195.21,39.127 194.999,39.548 195.21,39.97 194.788,39.759 194.367,39.97 194.577,39.548 194.367,39.127 ; 194.367,48.613 194.367,48.824 194.577,49.035 194.367,49.246 194.367,49.457 194.577,49.457 194.788,49.246 194.999,49.457 195.21,49.457 195.21,49.246 194.999,49.035 195.21,48.824 195.21,48.613 194.999,48.613 194.788,48.824 194.577,48.613 194.367,48.613
  lines w0.305: 192.811,31.572 243.064,31.572 ; 192.811,53.708 243.064,53.708 ; 201.397,28.41 201.397,56.871 ; 209.834,28.41 209.834,56.871 ; 226,28.41 226,56.871 ; 232.584,28.41 232.584,56.871 ; 192.811,28.41 243.064,28.41 243.064,56.871 192.811,56.871 192.811,28.41
  text ".legend" at 189.04,132.347 h1.52
  text "Drill Table" at 190.055,127.013 h1.52
  text "Symbol" at 194.709,54.657 h1.83
  text "Quantity" at 202.346,54.657 h1.83
  text "Finished Hole Size" at 210.782,54.657 h1.83
  text "Plated" at 226.949,54.657 h1.83
  text "Hole Type" at 233.533,54.657 h1.83
  text "193" at 202.346,51.495 h1.52
  text "11.81mil (0.300mm)" at 210.782,51.495 h1.52
  text "PTH" at 226.949,51.495 h1.52
  text "Round" at 233.533,51.495 h1.52
  text "A" at 194.066,51.241 h1.41
  text "1028" at 202.346,48.332 h1.52
  text "15.75mil (0.400mm)" at 210.782,48.332 h1.52
  text "PTH" at 226.949,48.332 h1.52
  text "Round" at 233.533,48.332 h1.52
  text "77" at 202.346,45.17 h1.52
  text "19.69mil (0.500mm)" at 210.782,45.17 h1.52
  text "PTH" at 226.949,45.17 h1.52
  text "Round" at 233.533,45.17 h1.52
  text "B" at 194.066,44.916 h1.41
  text "16" at 202.346,42.008 h1.52
  text "40.00mil (1.016mm)" at 210.782,42.008 h1.52
  text "PTH" at 226.949,42.008 h1.52
  text "Round" at 233.533,42.008 h1.52
  text "6" at 202.346,38.845 h1.52
  text "63.00mil (1.600mm)" at 210.782,38.845 h1.52
  text "PTH" at 226.949,38.845 h1.52
  text "Round" at 233.533,38.845 h1.52
  text "4" at 202.346,35.683 h1.52
  text "125.98mil (3.200mm)" at 210.782,35.683 h1.52
  text "PTH" at 226.949,35.683 h1.52
  text "Round" at 233.533,35.683 h1.52
  text "4" at 202.346,32.521 h1.52
  text "188.00mil (4.775mm)" at 210.782,32.521 h1.52
  text "PTH" at 226.949,32.521 h1.52
  text "Round" at 233.533,32.521 h1.52
  text "1328 Total" at 202.346,29.359 h1.52
  text ".Layer_Name" at 14.656,-21.806 h1.52

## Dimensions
-0.254,0 to 0,92.71 on M2 Board Dimensions
0,-0.381 to 108.204,0 on M2 Board Dimensions
0,-10.427 to 25.4,-10.427 on M2 Board Dimensions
